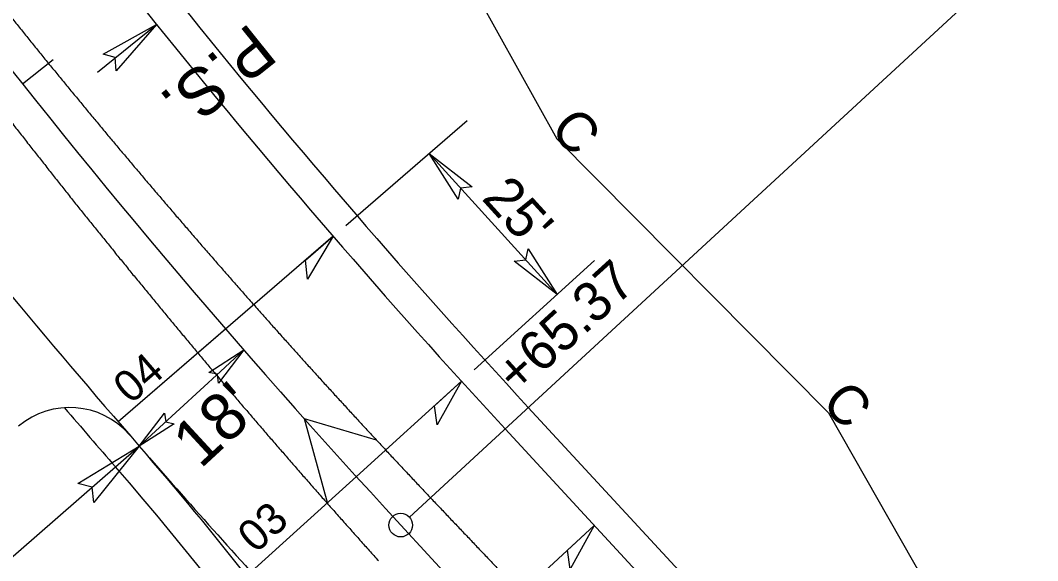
# Model space of a CAD drawing. Extents: x 1702862 to 1704514, y 793768 to 796215.
# Drawn here: x 1703198.5 to 1703327.4, y 795315.4 to 795384 of the extents above; entities that cross this region are included whole.
import ezdxf

# ---------------------------------------------------------------- set-up
doc = ezdxf.new("R2010")
doc.units = 0
for name, color, linetype in [('Prop Dimension', 7, 'Continuous'), ('Prop Dimension Text', 7, 'Continuous'), ('Prop EOT', 7, 'Continuous'), ('Prop Horizontal Alignment', 7, 'Continuous'), ('Prop Horizontal Alignment Station Label', 7, 'Continuous'), ('Prop Horizontal Alignment Tick Small', 7, 'Continuous'), ('Prop Lane Lines', 7, 'Continuous'), ('Prop Paint Stripe', 7, 'Continuous'), ('Prop Paved Shoulder', 7, 'Continuous'), ('Prop SS Cut Line', 7, 'Continuous'), ('Prop SS Misc', 7, 'Continuous'), ('Prop SS Transition Line', 7, 'Continuous'), ('Prop Superelevation  Arrow CELL', 7, 'Continuous'), ('Prop Superelevation Label', 7, 'Continuous'), ('Prop Terminator CELL', 7, 'Continuous')]:
    doc.layers.add(name, color=color, linetype=linetype)

msp = doc.modelspace()

# ---------------------------------------------------------------- linework, layer by layer
at = {"layer": 'Prop Dimension'}
for p, q in [((1703208.23, 795377.41), (1703215.73, 795383.44)), ((1703223.83, 795339.44), (1703226.77, 795342.16)), ((1703213.54, 795329.94), (1703223.83, 795339.44)), ((1702911.8, 795067.36), (1703213.54, 795329.94))]:
    msp.add_line(p, q, dxfattribs=at)
at = {"layer": 'Prop EOT'}
msp.add_line((1703259.9, 795332.15), (1703737.14, 794815.13), dxfattribs=at)
for centre, radius, start, end in [((1703981.48, 795998.22), 982, 215.01075, 222.70907), ((1703981.48, 795998.22), 1018, 215.01075, 221.03042), ((1703204.72, 795324.85), 10, 40.9218, 130.3644), ((1702911.8, 795067.36), 400, 28.6224, 41.0304)]:
    msp.add_arc(centre, radius, start, end, dxfattribs=at)
at = {"layer": 'Prop Horizontal Alignment'}
msp.add_line((1703246.67, 795319.94), (1703723.92, 794802.92), dxfattribs=at)
msp.add_arc((1703981.48, 795998.22), 1000, 201.8874, 222.70907, dxfattribs=at)
at = {"layer": 'Prop Horizontal Alignment Station Label'}
msp.add_line((1703247.78, 795320.96), (1703336.84, 795403.17), dxfattribs=at)
msp.add_circle((1703246.67, 795319.94), 1.5, dxfattribs=at)
at = {"layer": 'Prop Horizontal Alignment Tick Small'}
msp.add_line((1703198.73, 795375.89), (1703202.64, 795379), dxfattribs=at)
at = {"layer": 'Prop Lane Lines'}
msp.add_arc((1703981.48, 795998.22), 1018, 221.141, 222.70907, dxfattribs=at)
for points in [[(1703169.47, 795420.68), (1703169.98, 795419.98), (1703170.5, 795419.28), (1703171.01, 795418.58), (1703171.52, 795417.88), (1703172.03, 795417.19), (1703172.55, 795416.49), (1703173.06, 795415.79), (1703173.58, 795415.1), (1703174.09, 795414.4), (1703174.61, 795413.71), (1703175.13, 795413.01), (1703175.64, 795412.32), (1703176.16, 795411.63), (1703176.68, 795410.93), (1703177.2, 795410.24), (1703177.72, 795409.55), (1703178.24, 795408.86), (1703178.76, 795408.16), (1703179.28, 795407.47), (1703179.8, 795406.78), (1703180.33, 795406.09), (1703180.85, 795405.4), (1703181.37, 795404.72), (1703181.9, 795404.03), (1703182.42, 795403.34), (1703182.95, 795402.65), (1703183.48, 795401.96), (1703184, 795401.28), (1703184.53, 795400.59), (1703185.06, 795399.91), (1703185.59, 795399.22), (1703186.12, 795398.54), (1703186.65, 795397.85), (1703187.18, 795397.17), (1703187.71, 795396.48), (1703188.24, 795395.8), (1703188.77, 795395.12), (1703189.31, 795394.44), (1703189.84, 795393.76), (1703190.37, 795393.07), (1703190.91, 795392.39), (1703191.44, 795391.71), (1703191.98, 795391.03), (1703192.51, 795390.35), (1703193.05, 795389.68), (1703193.59, 795389), (1703194.13, 795388.32), (1703194.67, 795387.64), (1703195.21, 795386.97), (1703195.74, 795386.29), (1703196.29, 795385.61), (1703196.83, 795384.94), (1703197.37, 795384.26), (1703197.91, 795383.59), (1703198.45, 795382.92), (1703199, 795382.24), (1703199.54, 795381.57), (1703200.08, 795380.9), (1703200.63, 795380.22), (1703201.18, 795379.55), (1703201.72, 795378.88), (1703202.27, 795378.21), (1703202.82, 795377.54), (1703203.36, 795376.87), (1703203.91, 795376.2), (1703204.46, 795375.53), (1703205.01, 795374.87), (1703205.56, 795374.2), (1703206.11, 795373.53), (1703206.66, 795372.86), (1703207.21, 795372.2), (1703207.77, 795371.53), (1703208.32, 795370.87), (1703208.87, 795370.2)], [(1703163.88, 795416.71), (1703164.38, 795415.99), (1703164.87, 795415.28), (1703165.37, 795414.56), (1703165.87, 795413.84), (1703166.37, 795413.13), (1703166.86, 795412.41), (1703167.36, 795411.7), (1703167.86, 795410.98), (1703168.36, 795410.27), (1703168.86, 795409.56), (1703169.37, 795408.84), (1703169.87, 795408.13), (1703170.37, 795407.42), (1703170.88, 795406.71), (1703171.38, 795405.99), (1703171.88, 795405.28), (1703172.39, 795404.57), (1703172.9, 795403.86), (1703173.4, 795403.15), (1703173.91, 795402.44), (1703174.42, 795401.73), (1703174.93, 795401.03), (1703175.44, 795400.32), (1703175.94, 795399.61), (1703176.46, 795398.9), (1703176.97, 795398.2), (1703177.48, 795397.49), (1703177.99, 795396.79), (1703178.5, 795396.08), (1703179.02, 795395.38), (1703179.53, 795394.67), (1703180.05, 795393.97), (1703180.56, 795393.26), (1703181.08, 795392.56), (1703181.59, 795391.86), (1703182.11, 795391.16), (1703182.63, 795390.45), (1703183.15, 795389.75), (1703183.67, 795389.05), (1703184.19, 795388.35), (1703184.71, 795387.65), (1703185.23, 795386.95), (1703185.75, 795386.25), (1703186.27, 795385.55), (1703186.79, 795384.86), (1703187.32, 795384.16), (1703187.84, 795383.46), (1703188.37, 795382.76), (1703188.89, 795382.07), (1703189.42, 795381.37), (1703189.94, 795380.68), (1703190.47, 795379.98), (1703191, 795379.29), (1703191.53, 795378.59), (1703192.05, 795377.9), (1703192.58, 795377.2), (1703193.11, 795376.51), (1703193.64, 795375.82), (1703194.18, 795375.13), (1703194.71, 795374.44), (1703195.24, 795373.74), (1703195.77, 795373.05), (1703196.31, 795372.36), (1703196.84, 795371.67), (1703197.38, 795370.99), (1703197.91, 795370.3), (1703198.45, 795369.61), (1703198.98, 795368.92), (1703199.52, 795368.23), (1703200.06, 795367.55), (1703200.6, 795366.86), (1703201.14, 795366.17), (1703201.68, 795365.49), (1703202.22, 795364.8)], [(1703208.87, 795370.2), (1703209.43, 795369.54), (1703209.98, 795368.87), (1703210.54, 795368.21), (1703211.09, 795367.55), (1703211.65, 795366.89), (1703212.21, 795366.22), (1703212.77, 795365.56), (1703213.32, 795364.9), (1703213.88, 795364.24), (1703214.44, 795363.58), (1703215, 795362.92), (1703215.56, 795362.26), (1703216.12, 795361.61), (1703216.69, 795360.95), (1703217.25, 795360.29), (1703217.81, 795359.63), (1703218.37, 795358.98), (1703218.94, 795358.32), (1703219.5, 795357.67), (1703220.07, 795357.01), (1703220.63, 795356.36), (1703221.2, 795355.7), (1703221.76, 795355.05), (1703222.33, 795354.4), (1703222.9, 795353.75), (1703223.47, 795353.09), (1703224.04, 795352.44), (1703224.61, 795351.79), (1703225.18, 795351.14), (1703225.75, 795350.49), (1703226.32, 795349.84), (1703226.89, 795349.19), (1703227.46, 795348.54), (1703228.04, 795347.9), (1703228.61, 795347.25), (1703229.18, 795346.6), (1703229.76, 795345.96), (1703230.33, 795345.31), (1703230.91, 795344.67), (1703231.48, 795344.02), (1703232.06, 795343.38), (1703232.64, 795342.73), (1703233.22, 795342.09), (1703233.79, 795341.45), (1703234.37, 795340.8), (1703234.95, 795340.16), (1703235.53, 795339.52), (1703236.11, 795338.88), (1703236.69, 795338.24), (1703237.28, 795337.6), (1703237.86, 795336.96), (1703238.44, 795336.32), (1703239.02, 795335.69), (1703239.61, 795335.05), (1703240.19, 795334.41), (1703240.78, 795333.77), (1703241.36, 795333.14), (1703241.95, 795332.5), (1703242.54, 795331.87), (1703243.12, 795331.23), (1703243.71, 795330.6), (1703244.3, 795329.97), (1703244.89, 795329.33), (1703245.48, 795328.7), (1703246.07, 795328.07), (1703246.66, 795327.44), (1703247.25, 795326.81), (1703247.84, 795326.18), (1703248.43, 795325.55), (1703249.02, 795324.92), (1703249.62, 795324.29), (1703250.21, 795323.66), (1703250.8, 795323.03), (1703251.4, 795322.4)], [(1703202.22, 795364.8), (1703202.76, 795364.12), (1703203.3, 795363.43), (1703203.84, 795362.75), (1703204.38, 795362.07), (1703204.93, 795361.38), (1703205.47, 795360.7), (1703206.02, 795360.02), (1703206.56, 795359.34), (1703207.11, 795358.66), (1703207.65, 795357.98), (1703208.2, 795357.3), (1703208.75, 795356.62), (1703209.3, 795355.94), (1703209.85, 795355.26), (1703210.39, 795354.58), (1703210.94, 795353.9), (1703211.5, 795353.23), (1703212.05, 795352.55), (1703212.6, 795351.87), (1703213.15, 795351.2), (1703213.7, 795350.52), (1703214.26, 795349.85), (1703214.81, 795349.17), (1703215.37, 795348.5), (1703215.92, 795347.83), (1703216.48, 795347.15), (1703217.03, 795346.48), (1703217.59, 795345.81), (1703218.15, 795345.14), (1703218.71, 795344.47), (1703219.26, 795343.8), (1703219.82, 795343.13), (1703220.38, 795342.46), (1703220.94, 795341.79), (1703221.51, 795341.12), (1703222.07, 795340.45), (1703222.63, 795339.78), (1703223.19, 795339.12), (1703223.76, 795338.45), (1703224.32, 795337.78), (1703224.88, 795337.12), (1703225.45, 795336.45), (1703226.02, 795335.79), (1703226.58, 795335.12), (1703227.15, 795334.46), (1703227.72, 795333.8), (1703228.29, 795333.13), (1703228.85, 795332.47), (1703229.42, 795331.81), (1703229.99, 795331.15), (1703230.56, 795330.49), (1703231.13, 795329.83), (1703231.71, 795329.17), (1703232.28, 795328.51), (1703232.85, 795327.85), (1703233.42, 795327.19), (1703234, 795326.53), (1703234.57, 795325.88), (1703235.15, 795325.22), (1703235.72, 795324.56), (1703236.3, 795323.91), (1703236.88, 795323.25), (1703237.45, 795322.6), (1703238.03, 795321.94), (1703238.61, 795321.29), (1703239.19, 795320.63), (1703239.77, 795319.98), (1703240.35, 795319.33), (1703240.93, 795318.68), (1703241.51, 795318.03), (1703242.09, 795317.37), (1703242.68, 795316.72), (1703243.26, 795316.07), (1703243.84, 795315.43)], [(1703251.4, 795322.4), (1703252, 795321.77), (1703252.6, 795321.14), (1703253.19, 795320.51), (1703253.79, 795319.88), (1703254.39, 795319.25), (1703254.99, 795318.62), (1703255.59, 795317.99), (1703256.18, 795317.36), (1703256.78, 795316.73), (1703257.38, 795316.1), (1703257.98, 795315.47), (1703258.57, 795314.84), (1703259.17, 795314.21), (1703259.77, 795313.58), (1703260.37, 795312.95), (1703260.96, 795312.31), (1703261.56, 795311.68), (1703262.16, 795311.05), (1703262.76, 795310.42), (1703263.36, 795309.79), (1703263.95, 795309.16), (1703264.55, 795308.53), (1703265.15, 795307.9), (1703265.75, 795307.27), (1703266.34, 795306.64), (1703266.94, 795306.01), (1703267.54, 795305.38), (1703268.14, 795304.75), (1703268.74, 795304.12), (1703269.33, 795303.49), (1703269.93, 795302.86), (1703270.53, 795302.23), (1703271.13, 795301.6), (1703271.72, 795300.97), (1703272.32, 795300.34), (1703272.92, 795299.71), (1703273.52, 795299.07), (1703274.12, 795298.44), (1703274.71, 795297.81), (1703275.31, 795297.18), (1703275.91, 795296.55), (1703276.51, 795295.92), (1703277.1, 795295.29), (1703277.7, 795294.66), (1703278.3, 795294.03), (1703278.9, 795293.4), (1703279.49, 795292.77), (1703280.09, 795292.14), (1703280.69, 795291.51), (1703281.29, 795290.88), (1703281.89, 795290.25), (1703282.48, 795289.62), (1703283.08, 795288.99), (1703283.68, 795288.36), (1703284.28, 795287.73), (1703284.87, 795287.1), (1703285.47, 795286.46), (1703286.07, 795285.83), (1703286.67, 795285.2), (1703287.27, 795284.57), (1703287.86, 795283.94), (1703288.46, 795283.31), (1703289.06, 795282.68), (1703289.66, 795282.05), (1703290.25, 795281.42), (1703290.85, 795280.79), (1703291.45, 795280.16), (1703292.05, 795279.53), (1703292.65, 795278.9), (1703293.24, 795278.27), (1703293.84, 795277.64), (1703294.44, 795277.01), (1703295.63, 795275.75)]]:
    msp.add_spline(points, degree=3, dxfattribs=at)
at = {"layer": 'Prop Paint Stripe'}
for q in [(1703243.58, 795330.74), (1703237.38, 795322.68)]:
    msp.add_line((1703234.45, 795333.46), q, dxfattribs=at)
for points in [[(1703169.47, 795420.68), (1703169.98, 795419.98), (1703170.5, 795419.28), (1703171.01, 795418.58), (1703171.52, 795417.88), (1703172.03, 795417.19), (1703172.55, 795416.49), (1703173.06, 795415.79), (1703173.58, 795415.1), (1703174.09, 795414.4), (1703174.61, 795413.71), (1703175.13, 795413.01), (1703175.64, 795412.32), (1703176.16, 795411.63), (1703176.68, 795410.93), (1703177.2, 795410.24), (1703177.72, 795409.55), (1703178.24, 795408.86), (1703178.76, 795408.16), (1703179.28, 795407.47), (1703179.8, 795406.78), (1703180.33, 795406.09), (1703180.85, 795405.4), (1703181.37, 795404.72), (1703181.9, 795404.03), (1703182.42, 795403.34), (1703182.95, 795402.65), (1703183.48, 795401.96), (1703184, 795401.28), (1703184.53, 795400.59), (1703185.06, 795399.91), (1703185.59, 795399.22), (1703186.12, 795398.54), (1703186.65, 795397.85), (1703187.18, 795397.17), (1703187.71, 795396.48), (1703188.24, 795395.8), (1703188.77, 795395.12), (1703189.31, 795394.44), (1703189.84, 795393.76), (1703190.37, 795393.07), (1703190.91, 795392.39), (1703191.44, 795391.71), (1703191.98, 795391.03), (1703192.51, 795390.35), (1703193.05, 795389.68), (1703193.59, 795389), (1703194.13, 795388.32), (1703194.67, 795387.64), (1703195.21, 795386.97), (1703195.74, 795386.29), (1703196.29, 795385.61), (1703196.83, 795384.94), (1703197.37, 795384.26), (1703197.91, 795383.59), (1703198.45, 795382.92), (1703199, 795382.24), (1703199.54, 795381.57), (1703200.08, 795380.9), (1703200.63, 795380.22), (1703201.18, 795379.55), (1703201.72, 795378.88), (1703202.27, 795378.21), (1703202.82, 795377.54), (1703203.36, 795376.87), (1703203.91, 795376.2), (1703204.46, 795375.53), (1703205.01, 795374.87), (1703205.56, 795374.2), (1703206.11, 795373.53), (1703206.66, 795372.86), (1703207.21, 795372.2), (1703207.77, 795371.53), (1703208.32, 795370.87), (1703208.87, 795370.2)], [(1703163.88, 795416.71), (1703164.38, 795415.99), (1703164.87, 795415.28), (1703165.37, 795414.56), (1703165.87, 795413.84), (1703166.37, 795413.13), (1703166.86, 795412.41), (1703167.36, 795411.7), (1703167.86, 795410.98), (1703168.36, 795410.27), (1703168.86, 795409.56), (1703169.37, 795408.84), (1703169.87, 795408.13), (1703170.37, 795407.42), (1703170.88, 795406.71), (1703171.38, 795405.99), (1703171.88, 795405.28), (1703172.39, 795404.57), (1703172.9, 795403.86), (1703173.4, 795403.15), (1703173.91, 795402.44), (1703174.42, 795401.73), (1703174.93, 795401.03), (1703175.44, 795400.32), (1703175.94, 795399.61), (1703176.46, 795398.9), (1703176.97, 795398.2), (1703177.48, 795397.49), (1703177.99, 795396.79), (1703178.5, 795396.08), (1703179.02, 795395.38), (1703179.53, 795394.67), (1703180.05, 795393.97), (1703180.56, 795393.26), (1703181.08, 795392.56), (1703181.59, 795391.86), (1703182.11, 795391.16), (1703182.63, 795390.45), (1703183.15, 795389.75), (1703183.67, 795389.05), (1703184.19, 795388.35), (1703184.71, 795387.65), (1703185.23, 795386.95), (1703185.75, 795386.25), (1703186.27, 795385.55), (1703186.79, 795384.86), (1703187.32, 795384.16), (1703187.84, 795383.46), (1703188.37, 795382.76), (1703188.89, 795382.07), (1703189.42, 795381.37), (1703189.94, 795380.68), (1703190.47, 795379.98), (1703191, 795379.29), (1703191.53, 795378.59), (1703192.05, 795377.9), (1703192.58, 795377.2), (1703193.11, 795376.51), (1703193.64, 795375.82), (1703194.18, 795375.13), (1703194.71, 795374.44), (1703195.24, 795373.74), (1703195.77, 795373.05), (1703196.31, 795372.36), (1703196.84, 795371.67), (1703197.38, 795370.99), (1703197.91, 795370.3), (1703198.45, 795369.61), (1703198.98, 795368.92), (1703199.52, 795368.23), (1703200.06, 795367.55), (1703200.6, 795366.86), (1703201.14, 795366.17), (1703201.68, 795365.49), (1703202.22, 795364.8)], [(1703208.87, 795370.2), (1703209.43, 795369.54), (1703209.98, 795368.87), (1703210.54, 795368.21), (1703211.09, 795367.55), (1703211.65, 795366.89), (1703212.21, 795366.22), (1703212.77, 795365.56), (1703213.32, 795364.9), (1703213.88, 795364.24), (1703214.44, 795363.58), (1703215, 795362.92), (1703215.56, 795362.26), (1703216.12, 795361.61), (1703216.69, 795360.95), (1703217.25, 795360.29), (1703217.81, 795359.63), (1703218.37, 795358.98), (1703218.94, 795358.32), (1703219.5, 795357.67), (1703220.07, 795357.01), (1703220.63, 795356.36), (1703221.2, 795355.7), (1703221.76, 795355.05), (1703222.33, 795354.4), (1703222.9, 795353.75), (1703223.47, 795353.09), (1703224.04, 795352.44), (1703224.61, 795351.79), (1703225.18, 795351.14), (1703225.75, 795350.49), (1703226.32, 795349.84), (1703226.89, 795349.19), (1703227.46, 795348.54), (1703228.04, 795347.9), (1703228.61, 795347.25), (1703229.18, 795346.6), (1703229.76, 795345.96), (1703230.33, 795345.31), (1703230.91, 795344.67), (1703231.48, 795344.02), (1703232.06, 795343.38), (1703232.64, 795342.73), (1703233.22, 795342.09), (1703233.79, 795341.45), (1703234.37, 795340.8), (1703234.95, 795340.16), (1703235.53, 795339.52), (1703236.11, 795338.88), (1703236.69, 795338.24), (1703237.28, 795337.6), (1703237.86, 795336.96), (1703238.44, 795336.32), (1703239.02, 795335.69), (1703239.61, 795335.05), (1703240.19, 795334.41), (1703240.78, 795333.77), (1703241.36, 795333.14), (1703241.95, 795332.5), (1703242.54, 795331.87), (1703243.12, 795331.23), (1703243.71, 795330.6), (1703244.3, 795329.97), (1703244.89, 795329.33), (1703245.48, 795328.7), (1703246.07, 795328.07), (1703246.66, 795327.44), (1703247.25, 795326.81), (1703247.84, 795326.18), (1703248.43, 795325.55), (1703249.02, 795324.92), (1703249.62, 795324.29), (1703250.21, 795323.66), (1703250.8, 795323.03), (1703251.4, 795322.4)], [(1703202.22, 795364.8), (1703202.76, 795364.12), (1703203.3, 795363.43), (1703203.84, 795362.75), (1703204.38, 795362.07), (1703204.93, 795361.38), (1703205.47, 795360.7), (1703206.02, 795360.02), (1703206.56, 795359.34), (1703207.11, 795358.66), (1703207.65, 795357.98), (1703208.2, 795357.3), (1703208.75, 795356.62), (1703209.3, 795355.94), (1703209.85, 795355.26), (1703210.39, 795354.58), (1703210.94, 795353.9), (1703211.5, 795353.23), (1703212.05, 795352.55), (1703212.6, 795351.87), (1703213.15, 795351.2), (1703213.7, 795350.52), (1703214.26, 795349.85), (1703214.81, 795349.17), (1703215.37, 795348.5), (1703215.92, 795347.83), (1703216.48, 795347.15), (1703217.03, 795346.48), (1703217.59, 795345.81), (1703218.15, 795345.14), (1703218.71, 795344.47), (1703219.26, 795343.8), (1703219.82, 795343.13), (1703220.38, 795342.46), (1703220.94, 795341.79), (1703221.51, 795341.12), (1703222.07, 795340.45), (1703222.63, 795339.78), (1703223.19, 795339.12), (1703223.76, 795338.45), (1703224.32, 795337.78), (1703224.88, 795337.12), (1703225.45, 795336.45), (1703226.02, 795335.79), (1703226.58, 795335.12), (1703227.15, 795334.46), (1703227.72, 795333.8), (1703228.29, 795333.13), (1703228.85, 795332.47), (1703229.42, 795331.81), (1703229.99, 795331.15), (1703230.56, 795330.49), (1703231.13, 795329.83), (1703231.71, 795329.17), (1703232.28, 795328.51), (1703232.85, 795327.85), (1703233.42, 795327.19), (1703234, 795326.53), (1703234.57, 795325.88), (1703235.15, 795325.22), (1703235.72, 795324.56), (1703236.3, 795323.91), (1703236.88, 795323.25), (1703237.45, 795322.6), (1703238.03, 795321.94), (1703238.61, 795321.29), (1703239.19, 795320.63), (1703239.77, 795319.98), (1703240.35, 795319.33), (1703240.93, 795318.68), (1703241.51, 795318.03), (1703242.09, 795317.37), (1703242.68, 795316.72), (1703243.26, 795316.07), (1703243.84, 795315.43)], [(1703251.4, 795322.4), (1703252, 795321.77), (1703252.6, 795321.14), (1703253.19, 795320.51), (1703253.79, 795319.88), (1703254.39, 795319.25), (1703254.99, 795318.62), (1703255.59, 795317.99), (1703256.18, 795317.36), (1703256.78, 795316.73), (1703257.38, 795316.1), (1703257.98, 795315.47), (1703258.57, 795314.84), (1703259.17, 795314.21), (1703259.77, 795313.58), (1703260.37, 795312.95), (1703260.96, 795312.31), (1703261.56, 795311.68), (1703262.16, 795311.05), (1703262.76, 795310.42), (1703263.36, 795309.79), (1703263.95, 795309.16), (1703264.55, 795308.53), (1703265.15, 795307.9), (1703265.75, 795307.27), (1703266.34, 795306.64), (1703266.94, 795306.01), (1703267.54, 795305.38), (1703268.14, 795304.75), (1703268.74, 795304.12), (1703269.33, 795303.49), (1703269.93, 795302.86), (1703270.53, 795302.23), (1703271.13, 795301.6), (1703271.72, 795300.97), (1703272.32, 795300.34), (1703272.92, 795299.71), (1703273.52, 795299.07), (1703274.12, 795298.44), (1703274.71, 795297.81), (1703275.31, 795297.18), (1703275.91, 795296.55), (1703276.51, 795295.92), (1703277.1, 795295.29), (1703277.7, 795294.66), (1703278.3, 795294.03), (1703278.9, 795293.4), (1703279.49, 795292.77), (1703280.09, 795292.14), (1703280.69, 795291.51), (1703281.29, 795290.88), (1703281.89, 795290.25), (1703282.48, 795289.62), (1703283.08, 795288.99), (1703283.68, 795288.36), (1703284.28, 795287.73), (1703284.87, 795287.1), (1703285.47, 795286.46), (1703286.07, 795285.83), (1703286.67, 795285.2), (1703287.27, 795284.57), (1703287.86, 795283.94), (1703288.46, 795283.31), (1703289.06, 795282.68), (1703289.66, 795282.05), (1703290.25, 795281.42), (1703290.85, 795280.79), (1703291.45, 795280.16), (1703292.05, 795279.53), (1703292.65, 795278.9), (1703293.24, 795278.27), (1703293.84, 795277.64), (1703294.44, 795277.01), (1703295.63, 795275.75)]]:
    msp.add_spline(points, degree=3, dxfattribs=at)
at = {"layer": 'Prop Paved Shoulder'}
msp.add_line((1703262.84, 795334.86), (1703386.66, 795200.72), dxfattribs=at)
for centre, radius, start, end in [((1703981.48, 795998.22), 978, 215.01075, 222.70907), ((1703981.48, 795998.22), 1022, 220.47461, 221.03042), ((1702911.8, 795067.36), 396, 28.6224, 41.0304)]:
    msp.add_arc(centre, radius, start, end, dxfattribs=at)
at = {"layer": 'Prop SS Cut Line'}
for p, q in [((1703243.06, 795411.13), (1703266.46, 795368.92)), ((1703266.46, 795368.92), (1703300.88, 795334.19))]:
    msp.add_line(p, q, dxfattribs=at)
at = {"layer": 'Prop SS Transition Line'}
msp.add_line((1703300.88, 795334.19), (1703326.3, 795289.61), dxfattribs=at)
at = {"layer": 'Prop Superelevation  Arrow CELL'}
for p, q in [((1703238.11, 795356.57), (1703210.85, 795333.04)), ((1703224.48, 795344.8), (1703210.85, 795333.04)), ((1703241.05, 795326.09), (1703254.38, 795338.18)), ((1703241.05, 795326.09), (1703227.72, 795313.99)), ((1703257.98, 795307.69), (1703271.21, 795319.9))]:
    msp.add_line(p, q, dxfattribs=at)
for points in [[(1703238.11, 795356.57), (1703234.87, 795351.13), (1703234.6, 795353.54)], [(1703254.38, 795338.18), (1703251.28, 795332.67), (1703250.95, 795335.08)], [(1703271.21, 795319.9), (1703268.16, 795314.36), (1703267.81, 795316.76)]]:
    msp.add_lwpolyline(points, close=True, dxfattribs=at)
at = {"layer": 'Prop Superelevation Label'}
for p, q in [((1703239.71, 795357.95), (1703255.11, 795371.24)), ((1703250.27, 795367.06), (1703266.51, 795349.2)), ((1703255.99, 795339.65), (1703271.23, 795353.48))]:
    msp.add_line(p, q, dxfattribs=at)
for points in [[(1703253.95, 795361.29), (1703250.27, 795367.06), (1703255.72, 795362.85), (1703254.25, 795362.68)], [(1703262.83, 795354.97), (1703266.51, 795349.2), (1703261.06, 795353.41), (1703262.52, 795353.58)]]:
    msp.add_lwpolyline(points, close=True, dxfattribs=at)
at = {"layer": 'Prop Terminator CELL'}
for points in [[(1703208.94, 795379.68), (1703215.73, 795383.44), (1703210.59, 795377.56), (1703210.5, 795379.23)], [(1703222.37, 795339.3), (1703226.77, 795342.16), (1703223.57, 795337.95), (1703223.44, 795339.07)], [(1703217.95, 795332.8), (1703213.54, 795329.94), (1703216.74, 795334.15), (1703216.88, 795333.02)], [(1703205.74, 795325.2), (1703213.54, 795329.94), (1703207.77, 795322.79), (1703207.58, 795324.75)]]:
    msp.add_lwpolyline(points, close=True, dxfattribs=at)

# ---------------------------------------------------------------- texts
at = {"layer": 'Prop Dimension'}
msp.add_text('P.S.', height=6, rotation=218.7502, dxfattribs=at).set_placement((1703227.59, 795383.77))
at = {"layer": 'Prop Dimension Text'}
msp.add_text("18'", height=6, rotation=42.7091, dxfattribs=at).set_placement((1703221.28, 795326.98))
at = {"layer": 'Prop SS Misc'}
for rotation, p in [(311.3511, (1703265.44, 795370.07)), (312.7091, (1703299.84, 795335.32)), (312.7091, (1703299.84, 795335.32))]:
    msp.add_text('C', height=5, rotation=rotation, dxfattribs=at).set_placement(p)
at = {"layer": 'Prop Superelevation Label'}
for s, height, rotation, p in [("25'", 5, 312.2762, (1703256.81, 795361.32)), ('+65.37', 5, 42.2324, (1703261.49, 795336.36)), ('04', 4, 40.7994, (1703212.44, 795335.18)), ('03', 4, 42.2318, (1703228.29, 795316.25))]:
    msp.add_text(s, height=height, rotation=rotation, dxfattribs=at).set_placement(p)

doc.saveas('drawing.dxf')
